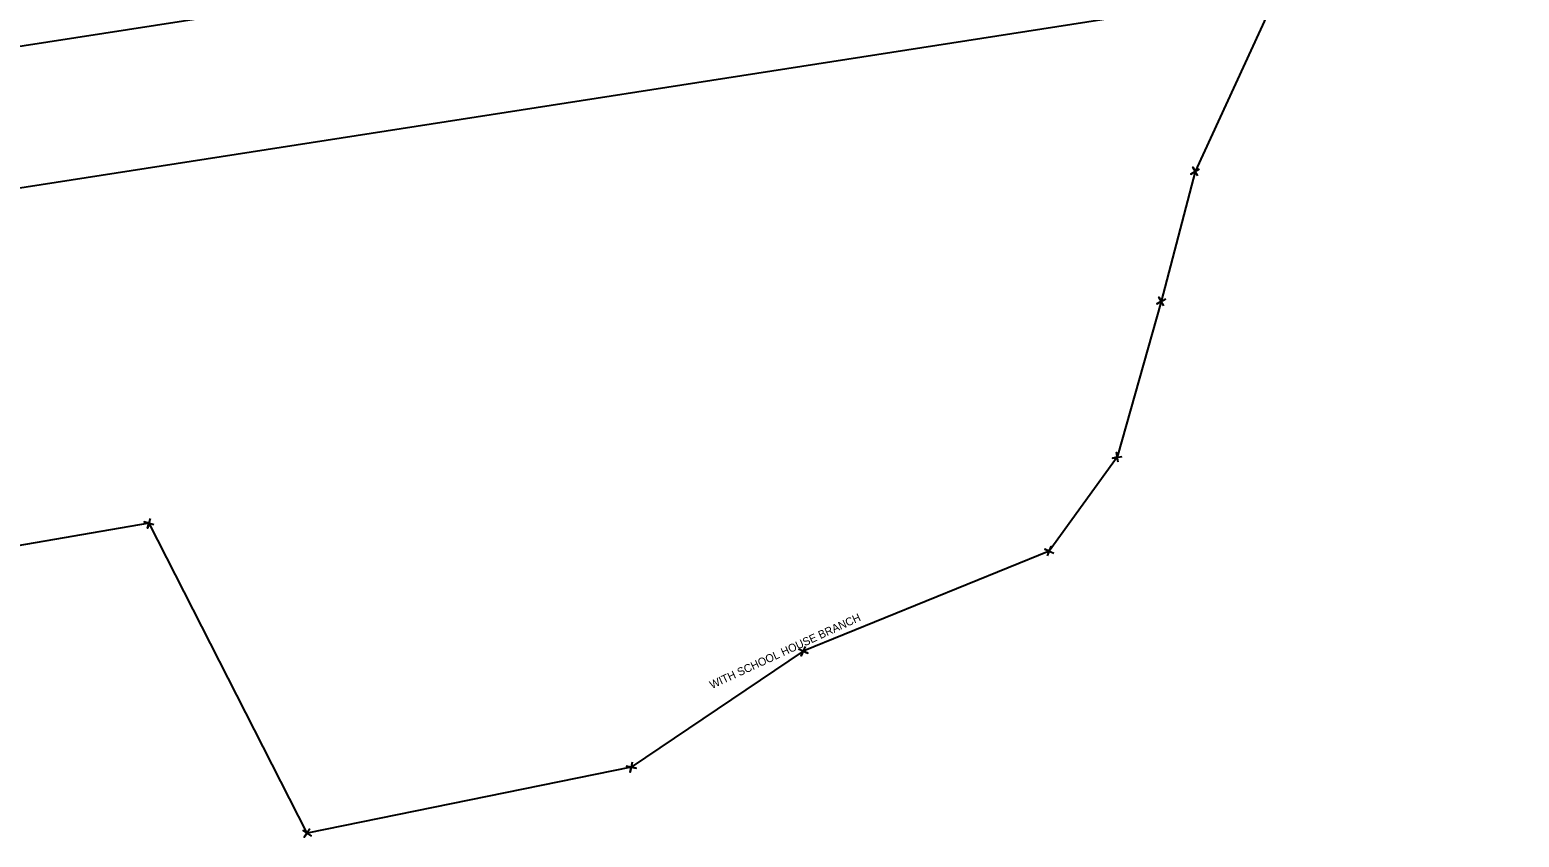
# Model space of a CAD drawing. Extents: x 2627243 to 2636458, y 566398 to 571062.
# Drawn here: x 2633704 to 2634449, y 568101 to 568505 of the extents above; entities that cross this region are included whole.
import ezdxf

# ---------------------------------------------------------------- set-up
doc = ezdxf.new("R2010")
doc.units = 0
for name, color, linetype in [('Exist Property Corner CELL', 7, 'Continuous'), ('Exist Property Line', 7, 'Continuous'), ('Exist Property Line Text', 7, 'Continuous'), ('Exist Right of Way Easement Line', 7, 'Continuous')]:
    doc.layers.add(name, color=color, linetype=linetype)

msp = doc.modelspace()

# ---------------------------------------------------------------- linework, layer by layer
at = {"layer": 'Exist Property Corner CELL'}
for p, q in [((2634287, 568434), (2634287, 568434)), ((2634270, 568369), (2634270, 568369)), ((2634248, 568291), (2634248, 568291)), ((2633764, 568258), (2633764, 568258)), ((2634214, 568244), (2634214, 568244)), ((2634091, 568194), (2634091, 568194)), ((2634005, 568136), (2634005, 568136)), ((2633843, 568103), (2633843, 568103))]:
    msp.add_line(p, q, dxfattribs=at)
for points in [[(2634288.26, 568431.84), (2634285.74, 568436.16), (2634287, 568434), (2634284.84, 568432.74), (2634289.16, 568435.26)], [(2634271.22, 568366.82), (2634268.78, 568371.18), (2634270, 568369), (2634267.82, 568367.78), (2634272.18, 568370.22)], [(2634248.4, 568288.53), (2634247.6, 568293.47), (2634248, 568291), (2634245.53, 568290.6), (2634250.47, 568291.4)], [(2633766.38, 568257.23), (2633761.62, 568258.77), (2633764, 568258), (2633763.23, 568255.62), (2633764.77, 568260.38)], [(2634213.03, 568241.7), (2634214.97, 568246.3), (2634214, 568244), (2634211.7, 568244.97), (2634216.3, 568243.03)], [(2634091.97, 568196.3), (2634090.03, 568191.7), (2634091, 568194), (2634093.3, 568193.03), (2634088.7, 568194.97)], [(2634005.48, 568138.45), (2634004.52, 568133.55), (2634005, 568136), (2634007.45, 568135.52), (2634002.55, 568136.48)], [(2633844.38, 568105.09), (2633841.62, 568100.91), (2633843, 568103), (2633845.09, 568101.62), (2633840.91, 568104.38)]]:
    msp.add_lwpolyline(points, dxfattribs=at)
at = {"layer": 'Exist Property Line'}
for p, q in [((2634331, 568530), (2634287, 568434)), ((2634287, 568434), (2634270, 568369)), ((2634270, 568369), (2634248, 568291)), ((2634248, 568291), (2634214, 568244)), ((2633764, 568258), (2633489, 568211)), ((2633843, 568103), (2633764, 568258)), ((2634214, 568244), (2634091, 568194)), ((2634091, 568194), (2634005, 568136)), ((2634005, 568136), (2633843, 568103))]:
    msp.add_line(p, q, dxfattribs=at)
at = {"layer": 'Exist Right of Way Easement Line'}
for p, q in [((2633122.32, 568406.7), (2634437.06, 568611.63)), ((2632896.01, 568300.58), (2634448.9, 568542.63))]:
    msp.add_line(p, q, dxfattribs=at)

# ---------------------------------------------------------------- texts
at = {"layer": 'Exist Property Line Text'}
msp.add_text('WITH SCHOOL HOUSE BRANCH', height=4, rotation=24.69374, dxfattribs=at).set_placement((2634045.36, 568175.07))

doc.saveas('drawing.dxf')
